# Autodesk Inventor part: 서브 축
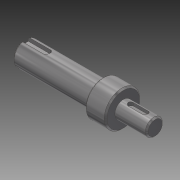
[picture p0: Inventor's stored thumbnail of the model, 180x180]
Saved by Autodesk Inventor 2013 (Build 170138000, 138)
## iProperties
Created: 2014-10
Part Number: 서브 축
Document SubType Name: Modeling
Designer: KYOUNG IL JANG
Density: 1 g/cm^3
Mass: 19.9624 g
Surface Area: 57.7178 cm^2
Volume: 19.9624 cm^3
Material: 강철, 연강
Author: SeoGD™ [www.esajin.kr]
Revision Number: 1
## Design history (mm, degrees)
sketch "스케치1"
  geometry: L1 (-16.331, 0)-(-108.331, 0); L2 (-16.331, 0)-(-16.331, -6); L3 (-16.331, -6)-(-38.831, -6); L4 (-38.831, -12.5)-(-53.5, -12.5); L5 (-53.5, -8.5)-(-108.331, -8.5); L6 (-108.331, -8.5)-(-108.331, 0); L7 (-53.5, -8.5)-(-53.5, -12.5); L8 (-38.831, -6)-(-38.831, -12.5); L9 (-46.5, 12.249)-(-46.5, -12.249) reference; L10 (-38.831, -17)-(-38.831, 17) reference; L11 (-53.5, 26)-(-53.5, -26) reference; C1 r 37 at (2.5, 0) reference; 2 further points
  constraints: 17 end point, 4 perpendicular, 2 parallel, 1 collinear, 1 horizontal, 1 midpoint, 1 point on line
  dimensions: "d1" = 12 diameter of L3 L1; "d2" = 25 diameter of L4 L1; "d3" = 17 diameter of L5 L1; "d18" = 22.5 distance of L2.end L3.end; "d34" = 56 distance from line of L7 C1.centre; "d35" = 92 distance between parallel lines of L2 L6
revolve "회전1" sketch "스케치1" stored, may be unused: angle "d5" = 90 deg
node "작업 평면1"
chamfer "모따기1" distance "d6" = 1; stored, may be unused: second distance "d7" = 2, angle "d8" = 45 deg
sketch "스케치2"
  geometry: L1 (11.25, 5)-(11.25, -5) reference; L2 (-5.75, -2)-(4.25, -2); L3 (4.25, 2)-(-5.75, 2); A1 r 2 centre (4.25, 0) between (4.25, -2) and (4.25, 2); A2 r 2 centre (-5.75, 0) between (-5.75, 2) and (-5.75, -2); 2 further points
  constraints: 4 end point, 4 point on circle, 4 tangent, 2 centre point, 1 horizontal alignment, 1 midpoint, 1 parallel, 1 perpendicular
  dimensions: "d9" = 4 distance between parallel lines of L2 L3; "d10" = 14 dimension on A1 A2; "d11" = 5 distance edge to line of A1 L1
extrude "돌출1" cut sketch "스케치2" distance "d12" = 2.5; taper "d13" = 0 deg
node "작업 평면2"
sketch "스케치3"
  geometry: L1 (-27.416, -7.5)-(-27.416, 7.5) reference; L2 (-27.416, 2.5)-(-11.916, 2.5); L3 (-11.916, -2.5)-(-27.416, -2.5); A1 r 2.5 centre (-11.916, 0) between (-11.916, -2.5) and (-11.916, 2.5); 2 further points
  constraints: 4 end point, 2 perpendicular, 2 point on circle, 2 point on line, 2 tangent, 1 centre point, 1 horizontal alignment, 1 midpoint
  dimensions: "d14" = 5 distance between parallel lines of L3 L2; "d15" = 18 dimension on A1 L1
extrude "돌출2" cut sketch "스케치3" distance "d16" = 3; taper "d17" = 0 deg
node "솔리드1"
node "참조4"
node "참조5"
node "참조6"
node "참조7"
